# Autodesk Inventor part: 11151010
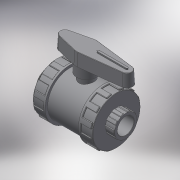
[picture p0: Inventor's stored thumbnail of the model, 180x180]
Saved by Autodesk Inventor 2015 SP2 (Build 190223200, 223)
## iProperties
Created: 2017-11
Part Number: 11151010
Material: Generic
Description: 2/NUT VALVE FEMALE THREAD 1" PVC
Document SubType Name: Modeling
Designer: KIM
Density: 1 g/cm^3
Appearance: Default
Author: KIM
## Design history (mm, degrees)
derived "111510.ipt"
feature "Solid1::111510.ipt"
tag "TaggingFeature1"
body "Solid1"
other parameters: "d0" = 102, "d1" = 30.291, "d2" = 66, "d3" = 19, "d4" = 24.2328, "d5" = 13.3, "d7" = 42.4074, "d8" = 59.4, "d13" = 0.90873, "d23" = 19, "d24" = 63.36, "d25" = 0.60582, "d26" = 0.90873, "d27" = 9.9, "d28" = 4.95, "d29" = 14.25, "d30" = 0, "d35" = 0.90873, "d39" = 33, "d45" = 360 deg, "d47" = 0.60582, "d50" = 36.3, "d51" = 19.8, "d53" = 0, "d55" = 6.0582, "d56" = 3.0291, "d57" = 13.3, "d58" = 0, "d59" = 0.90873, "d61" = 360 deg, "d63" = 26.4, "d64" = 66, "d66" = 78, "d68" = 13.2, "d69" = 23.4, "d70" = 16.5, "d71" = 3 deg, "d73" = 1.32, "d74" = 31.2, "d75" = 1.98, "d76" = 0, "d77" = 0.60582, "G_" = 30.291, "l_" = 19, "H_" = 102, "K_" = 66, "F_" = 66, "J_" = 78, "d67" = 26.4, "d72" = 6.6
